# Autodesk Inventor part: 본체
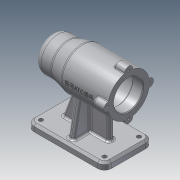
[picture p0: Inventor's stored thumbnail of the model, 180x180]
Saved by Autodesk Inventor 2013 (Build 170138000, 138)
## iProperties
Created: 2019-07
Part Number: 본체
Material: 알루미늄 6061
Document SubType Name: Modeling
Designer: 12
Density: 2.71 g/cm^3
Mass: 646.085 g
Surface Area: 655.731 cm^2
Volume: 238.408 cm^3
Author: 12
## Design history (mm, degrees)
sketch "스케치1"
  geometry: L1 (-56, 0)-(56, 0); L2 (-56, 0)-(-56, 25); L3 (-56, 25)-(-31, 25); L4 (-31, 25)-(-11, 30); L5 (-11, 30)-(56, 30); L6 (56, 30)-(56, 0); 2 further points
  constraints: 12 end point, 2 parallel, 2 perpendicular, 1 coincident, 1 horizontal, 1 midpoint
  dimensions: "d0" = 112 distance of L1.start L1.end; "d1" = 60 diameter of L5 L1; "d2" = 50 diameter of L3 L1; "d3" = 45 distance from line of L4.end L2; "d4" = 25 distance of L2.end L3.end
revolve "회전1" sketch "스케치1" stored, may be unused: angle "d5" = 90 deg
sketch "스케치2"
  geometry: C1 r 30 at (0, 0) reference; C2 r 21 at (0, 0)
  constraints: 1 centre point, 1 coincident
  dimensions: "d6" = 42 diameter of C2
extrude "돌출1" cut sketch "스케치2" distance "d7" = 15; taper "d8" = 0 deg
sketch "스케치3"
  geometry: C1 r 21 at (0, 0) reference; C2 r 24 at (0, 0)
  constraints: 1 centre point, 1 coincident
  dimensions: "d9" = 48 diameter of C2
extrude "돌출2" cut sketch "스케치3" distance "d10" = 54; taper "d11" = 0 deg
sketch "스케치4"
  geometry: C1 r 24 at (0, 0) reference; C2 r 21 at (0, 0)
  constraints: 1 centre point, 1 coincident
  dimensions: "d12" = 42 diameter of C2
extrude "돌출3" cut sketch "스케치4" distance "d13" = 12; taper "d14" = 0 deg
sketch "스케치5"
  geometry: C1 r 21 at (0, 0) reference; C2 r 17.5 at (0, 0)
  constraints: 1 centre point, 1 coincident
  dimensions: "d15" = 35 diameter of C2
extrude "돌출4" cut sketch "스케치5" distance "d16" = 18; taper "d17" = 0 deg
sketch "스케치6"
  geometry: C1 r 17.5 at (0, 0) reference; C2 r 16 at (0, 0)
  constraints: 1 centre point, 1 coincident
  dimensions: "d18" = 32 diameter of C2
extrude "돌출5" cut sketch "스케치6" distance "d19" = 4; taper "d20" = 0 deg
sketch "스케치8"
  geometry: L1 (0, 0)-(0, 30); C1 r 30 at (0, 0) reference; C2 r 6 at (0, 30)
  constraints: 2 end point, 1 centre point, 1 coincident, 1 vertical
  dimensions: "d26" = 30 distance of L1.start L1.end; "d27" = 12 diameter of C2
extrude "돌출6" join sketch "스케치8" distance "d28" = 16; taper "d29" = 0 deg
sketch "스케치9"
  geometry: A1 r 6 centre (0, 0) between (5.97, -0.6) and (-5.97, -0.6) reference; A2 r 6 centre (-30, -30) between (-29.4, -24.03) and (-29.4, -35.97) reference; A3 r 6 centre (0, -60) between (-5.97, -59.4) and (5.97, -59.4) reference; A4 r 6 centre (30, -30) between (29.4, -35.97) and (29.4, -24.03) reference; 4 further points
  constraints: 4 coincident
hole "구멍1" sketch "스케치9" at (0, 0), (30, -30), (-30, -30), (0, -60) diameter "d33" = 3.242; stored, may be unused: countersink angle "d37" = 90 deg, drill point angle "d39" = 118 deg; dims "d34" = 8, "d35" = 4, "d36" = 2, "d38" = 11
sketch "스케치10"
  geometry: C1 r 16 at (0, 0) reference; C2 r 10.5 at (0, 0)
  constraints: 1 centre point, 1 coincident
  dimensions: "d41" = 21 diameter of C2
extrude "돌출7" cut sketch "스케치10" distance "d42" = 3; taper "d43" = 0 deg
node "작업 평면1"
sketch "스케치11"
  geometry: L1 (56, 35)-(-56, 35); L2 (-56, 35)-(-56, -35); L3 (-56, -35)-(56, -35); L4 (56, -35)-(56, 35); L5 (56, 5.97)-(56, 29.4) reference; L6 (56, 6)-(56, -6) reference; L7 (56, -29.4)-(56, -5.97) reference; L8 (56, -29.4)-(56, -36) reference; L9 (56, 36)-(56, 29.4) reference; 2 further points
  constraints: 8 end point, 2 midpoint, 2 parallel, 1 horizontal, 1 perpendicular
  dimensions: "d45" = 112 distance of L3.end L2.end; "d46" = 70 distance of L2.end L1.end
extrude "돌출8" join sketch "스케치11" distance "d47" = 10; taper "d48" = 0 deg
fillet "모깎기1" dims "d60" = 10
sketch "스케치14"
  geometry: A1 r 10 centre (-46, 25) between (-46, 35) and (-56, 25) reference; A2 r 10 centre (-46, -25) between (-56, -25) and (-46, -35) reference; A3 r 10 centre (46, -25) between (46, -35) and (56, -25) reference; A4 r 10 centre (46, 25) between (56, 25) and (46, 35) reference; 5 further points
  constraints: 4 coincident
hole "구멍2" sketch "스케치14" at (-46, 25), (46, 25), (-46, -25), (46, -25) diameter "d61" = 6; stored, may be unused: countersink angle "d65" = 90 deg, drill point angle "d67" = 118 deg; dims "d62" = 8, "d63" = 4, "d64" = 2, "d66" = 11
fillet "모깎기2" dims "d68" = 10
fillet "모깎기3" dims "d69" = 0.3
fillet "모깎기4" dims "d70" = 3
fillet "모깎기5" dims "d71" = 3
chamfer "모따기1" distance "d72" = 1; stored, may be unused: second distance "d73" = 2, angle "d74" = 45 deg
chamfer "모따기2" distance "d75" = 3; stored, may be unused: second distance "d76" = 2, angle "d77" = 45 deg
sketch "스케치20"
  geometry: L1 (4, 4)-(31, 4); L2 (31, 4)-(31, -4); L3 (31, -4)-(4, -4); L4 (4, -4)-(4, 4); L5 (56, -25)-(56, 25) reference; 1 further point
  constraints: 8 end point, 2 parallel, 1 horizontal, 1 perpendicular
  dimensions: "d103" = 25 distance between parallel lines of L5 L2
extrude "돌출12" join sketch "스케치20" stored distance "d104" = 8; taper "d105" = 0 deg
fillet "모깎기6" dims "d78" = 3
fillet "모깎기7" dims "d79" = 3
fillet "모깎기8" dims "d80" = 1
node "작업 평면2"
sketch "스케치16"
  geometry: L1 (56, 6.771)-(56, 29.226) reference; L2 (56, 36)-(56, 30.171) reference; 2 further points
  constraints: 1 horizontal alignment, 1 other
  dimensions: "d85" = 42 distance from line of L2 point (14, 0)
feature "엠보싱1" sketch "스케치16" dims "d0" = 112, "d1" = 60, "d2" = 50, "d3" = 45, "d4" = 25, "d10" = 54, "d86" = 0.5, "d87" = 0
sketch "스케치17"
  geometry: L1 (45, -28.379)-(44.026, -30) reference; L2 (44.026, -30)-(45, -31.621) reference; L3 (45, -31.621)-(56, -31.621) reference; L4 (56, -31.621)-(56, -36) reference; L5 (56, -36)-(43, -36) reference; L6 (40, -33)-(40, -31) reference; L7 (39, -30)-(31, -30) reference; L8 (31, -70)-(53, -70) reference; L9 (53, -70)-(56, -73) reference; L10 (56, -73)-(56, -80) reference; L11 (56, -80)-(-56, -80) reference; L12 (-56, -80)-(-56, -73) reference; L13 (-56, -73)-(-53, -70) reference; L14 (-53, -70)-(4, -70) reference; L15 (4, -30)-(-11, -30) reference; L16 (-11, -30)-(-31, -25) reference; L17 (-31, -25)-(-46, -25) reference; L18 (-56, -15)-(-56, 15) reference; L19 (-46, 25)-(-31, 25) reference; L20 (-31, 25)-(-11, 30) reference; L21 (-11, 30)-(39, 30) reference; L22 (40, 31)-(40, 33) reference; L23 (43, 36)-(56, 36) reference; L24 (56, 36)-(56, 31.621) reference; L25 (56, 31.621)-(45, 31.621) reference; L26 (45, 31.621)-(44.026, 30) reference; L27 (44.026, 30)-(45, 28.379) reference; L28 (45, 28.379)-(56, 28.379) reference; L29 (56, 28.379)-(56, 22) reference; L30 (56, 22)-(55, 21) reference; L31 (55, 21)-(41, 21) reference; L32 (38, 24)-(-10, 24) reference; L33 (-13, 21)-(-24.7, 21) reference; L34 (-25, 20.7)-(-25, 17.5) reference; L35 (-25, 17.5)-(-42.7, 17.5) reference; L36 (-43, 17.2)-(-43, 16) reference; L37 (-43, 16)-(-46.7, 16) reference; L38 (-47, 15.7)-(-47, 10.5) reference; L39 (-50, 7.5)-(-50, -7.5) reference; L40 (-47, -10.5)-(-47, -15.7) reference; L41 (-46.7, -16)-(-43, -16) reference; L42 (-43, -16)-(-43, -17.2) reference; L43 (-42.7, -17.5)-(-25, -17.5) reference; L44 (-25, -17.5)-(-25, -20.7) reference; L45 (-24.7, -21)-(-13, -21) reference; L46 (-10, -24)-(38, -24) reference; L47 (41, -21)-(55, -21) reference; L48 (55, -21)-(56, -22) reference; L49 (56, -22)-(56, -28.379) reference; L50 (56, -28.379)-(45, -28.379) reference; L51 (-20.57, -27.607)-(-36, -70); L52 (31, -30)-(31, -70) reference; L53 (4, -70)-(4, -30) reference; A1 r 3 centre (43, -33) between (40, -33) and (43, -36) reference; A2 r 1 centre (39, -31) between (40, -31) and (39, -30) reference; A3 r 10 centre (-46, -15) between (-56, -15) and (-46, -25) reference; A4 r 10 centre (-46, 15) between (-46, 25) and (-56, 15) reference; A5 r 1 centre (39, 31) between (39, 30) and (40, 31) reference; A6 r 3 centre (43, 33) between (43, 36) and (40, 33) reference; A7 r 3 centre (38, 21) between (41, 21) and (38, 24) reference; A8 r 3 centre (-10, 21) between (-10, 24) and (-13, 21) reference; A9 r 0.3 centre (-24.7, 20.7) between (-24.7, 21) and (-25, 20.7) reference; A10 r 0.3 centre (-42.7, 17.2) between (-42.7, 17.5) and (-43, 17.2) reference; A11 r 0.3 centre (-46.7, 15.7) between (-46.7, 16) and (-47, 15.7) reference; A12 r 3 centre (-47, 7.5) between (-47, 10.5) and (-50, 7.5) reference; A13 r 3 centre (-47, -7.5) between (-50, -7.5) and (-47, -10.5) reference; A14 r 0.3 centre (-46.7, -15.7) between (-47, -15.7) and (-46.7, -16) reference; A15 r 0.3 centre (-42.7, -17.2) between (-43, -17.2) and (-42.7, -17.5) reference; A16 r 0.3 centre (-24.7, -20.7) between (-25, -20.7) and (-24.7, -21) reference; A17 r 3 centre (-10, -21) between (-13, -21) and (-10, -24) reference; A18 r 3 centre (38, -21) between (38, -24) and (41, -21) reference; 1 further point
  constraints: 2 end point, 2 point on line
  dimensions: "d88" = 110 deg angle of L14 L51; "d89" = 20 distance from line of L12 L51.end
feature "리브1" sketch "스케치17" dims "d90" = 1, "d91" = 8, "d92" = 0, "d93" = 0, "d94" = 1, "d95" = 1
sketch "스케치21"
  geometry: L1 (-70, 32)-(-70, 4) reference; L2 (-70, 4)-(-29.732, 4) reference; L3 (0.254, 29.999)-(0.254, 30.499) reference; L4 (0.648, 30.493)-(0.648, 29.993) reference; L5 (-29.732, -4)-(-70, -4) reference; L6 (-70, -4)-(-70, -32) reference; L7 (-70, -32)-(-73, -35) reference; L8 (-73, -35)-(-80, -35) reference; L9 (-80, -35)-(-80, 35) reference; L10 (-80, 35)-(-73, 35) reference; L11 (-73, 35)-(-70, 32) reference; L12 (-22.666, 19.654)-(-70, 28); C1 r 24 at (0, 0) reference; A1 r 30 centre (0, 0) between (0.254, 29.999) and (-29.732, 4) reference; A2 r 30.5 centre (0, 0) between (0.648, 30.493) and (0.254, 30.499) reference; A3 r 30 centre (0, 0) between (-29.732, -4) and (0.648, 29.993) reference; 1 further point
  constraints: 2 end point, 1 point on circle, 1 point on line
  dimensions: "d106" = 7 distance from line of L10 L12.end; "d107" = 100 deg angle of L1 L12
feature "리브2" sketch "스케치21" dims "d108" = 1, "d109" = 8, "d110" = 0, "d111" = 0, "d112" = 1, "d113" = 1
fillet "모깎기14" dims "d114" = 3
fillet "모깎기15" dims "d115" = 3
chamfer "모따기3" distance "d116" = 1; stored, may be unused: second distance "d117" = 2, angle "d118" = 45 deg
node "솔리드1"
pattern_circular "원형 패턴1" dims angle "d31" = 360 deg
mirror "대칭1"
node "절단 모서리 투영4"
node "절단 모서리 투영7"
